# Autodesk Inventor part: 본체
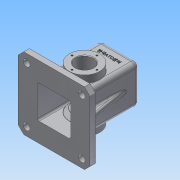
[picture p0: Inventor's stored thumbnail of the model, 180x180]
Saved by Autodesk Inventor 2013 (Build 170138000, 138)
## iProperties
Created: 2016-02
Part Number: 본체
Material: 알루미늄 6061
Document SubType Name: Modeling
Designer: Administrator
Density: 2.71 g/cm^3
Mass: 932.811 g
Surface Area: 1043.48 cm^2
Volume: 344.211 cm^3
Author: Administrator
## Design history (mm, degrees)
sketch "스케치1"
  geometry: L1 (35, -35)-(-35, -35); L2 (-35, -35)-(-35, 35); L3 (-35, 35)-(35, 35); L4 (35, 35)-(35, -35); L5 (35, -35)-(-35, 35); L6 (-35, -35)-(35, 35); 1 further point
  constraints: 12 end point, 2 midpoint, 2 parallel, 1 horizontal, 1 perpendicular
  dimensions: "d0" = 70 distance of L2.end L3.end; "d1" = 70 distance of L1.end L2.end
extrude "돌출1" new body sketch "스케치1" distance "d2" = 65; taper "d4" = 0 deg; dims "d3" = 55, "d5" = 0
fillet "모깎기1" dims "d6" = 8
fillet "모깎기2" dims "d7" = 8
feature "쉘1" dims "d8" = 5
sketch "스케치2"
  geometry: L1 (-27, -35)-(27, -35) reference; L2 (35, -27)-(35, 27) reference; L3 (27, 35)-(-27, 35) reference; L4 (-35, 27)-(-35, -27) reference; L5 (-65, 65)-(65, 65); L6 (65, 65)-(65, -65); L7 (65, -65)-(-65, -65); L8 (-65, -65)-(-65, 65); L9 (-65, 65)-(65, -65); L10 (65, 65)-(-65, -65); A1 r 8 centre (-27, -27) between (-35, -27) and (-27, -35) reference; A2 r 8 centre (27, -27) between (27, -35) and (35, -27) reference; A3 r 8 centre (27, 27) between (35, 27) and (27, 35) reference; A4 r 8 centre (-27, 27) between (-27, 35) and (-35, 27) reference; 1 further point
  constraints: 12 end point, 2 midpoint, 2 parallel, 1 horizontal, 1 perpendicular
  dimensions: "d9" = 130 distance of L6.end L7.end; "d10" = 130 distance of L5.end L6.end
extrude "돌출2" join sketch "스케치2" distance "d11" = 10; taper "d12" = 0 deg
sketch "스케치3"
  geometry: C1 r 27.5 at (27, -57); 1 further point
  constraints: 1 centre point, 1 coincident
  dimensions: "d13" = 55 diameter of C1
extrude "돌출3" join sketch "스케치3" distance "d14" = 13; taper "d15" = 0 deg
sketch "스케치4"
  geometry: C1 r 27.5 at (27, -57); 1 further point
  constraints: 1 centre point, 1 coincident
  dimensions: "d16" = 55 diameter of C1
extrude "돌출4" join sketch "스케치4" distance "d17" = 7; taper "d18" = -45 deg
sketch "스케치5"
  geometry: C1 r 20 at (0, 0); 1 further point
  constraints: 1 centre point, 1 coincident
  dimensions: "d19" = 40 diameter of C1
extrude "돌출5" join sketch "스케치5" distance "d20" = 10; taper "d21" = -10 deg
sketch "스케치7"
  geometry: C1 r 27.5 at (0, 0) reference; C2 r 16 at (0, 0)
  constraints: 1 centre point, 1 coincident
  dimensions: "d25" = 32 diameter of C2
extrude "돌출7" cut sketch "스케치7" stored distance "d26" = 10; taper "d27" = 0 deg
fillet "모깎기3" dims "d28" = 0.5
chamfer "모따기1" distance "d29" = 1; stored, may be unused: second distance "d30" = 2, angle "d31" = 45 deg
fillet "모깎기4" dims "d32" = 0.5
fillet "모깎기5" dims "d33" = 3
sketch "스케치8"
  geometry: L1 (65, -55)-(65, -45) reference; L2 (65, -45)-(-65, -45) reference; L3 (50, -45)-(35, 40.069); L4 (50, -45)-(150.19, -45); L5 (35, 57)-(35, -45) reference; 1 further point
  constraints: 4 end point, 2 point on line, 1 horizontal
  dimensions: "d34" = 100 deg angle of L4 L3; "d35" = 15 distance of L1.end L3.start
feature "리브1" sketch "스케치8" dims "d36" = 1, "d37" = 10, "d38" = 0, "d39" = 0, "d40" = 1, "d41" = 1
fillet "모깎기6" dims "d42" = 3
fillet "모깎기7" dims "d43" = 3
chamfer "모따기2" distance "d44" = 10; stored, may be unused: second distance "d45" = 2, angle "d46" = 45 deg
sketch "스케치9"
  geometry: L1 (55, 65)-(-55, 65) reference; L2 (65, -55)-(65, 55) reference; 2 further points
  dimensions: "d47" = 15 distance from line of L2 point (50, 50); "d48" = 15 distance from line of L1 point (50, 50)
hole "구멍1" sketch "스케치9" at (50, 50) diameter "d49" = 12; stored, may be unused: countersink angle "d53" = 90 deg, drill point angle "d55" = 118 deg; dims "d50" = 6, "d51" = 4, "d52" = 2, "d54" = 8
fillet "모깎기8" dims "d59" = 3
sketch "스케치10"
  geometry: C1 r 27.5 at (0, 0) reference; 1 further point
  constraints: 1 vertical alignment
  dimensions: "d60" = 22.5 distance of C1.centre point (0, 22.5)
hole "구멍2" sketch "스케치10" at (0, 22.5) diameter "d61" = 3.242; stored, may be unused: countersink angle "d65" = 90 deg, drill point angle "d67" = 118 deg; dims "d62" = 8, "d63" = 4, "d64" = 2, "d66" = 10
hole "구멍3" diameter "d73" = 21; stored, may be unused: countersink angle "d77" = 90 deg, drill point angle "d79" = 118 deg; dims "d71" = 10, "d72" = 10, "d74" = 8, "d75" = 28, "d76" = 4, "d78" = 10
sketch "스케치11"
  geometry: L1 (62, -99)-(62, 0) reference; L2 (8.763, 18)-(45.237, 18) reference; 1 further point
  constraints: 1 other
  dimensions: "d80" = 35 distance from line of L1 point (27, -12); "d81" = 30 distance from line of L2 point (27, -12)
feature "엠보싱1" sketch "스케치11" dims "d0" = 70, "d1" = 70, "d82" = 0.5, "d83" = 0
node "솔리드1"
mirror "대칭1"
mirror "대칭2"
mirror "대칭3"
pattern_circular "원형 패턴1" dims angle "d57" = 360 deg
pattern_circular "원형 패턴2" dims angle "d69" = 360 deg
mirror "대칭4"
